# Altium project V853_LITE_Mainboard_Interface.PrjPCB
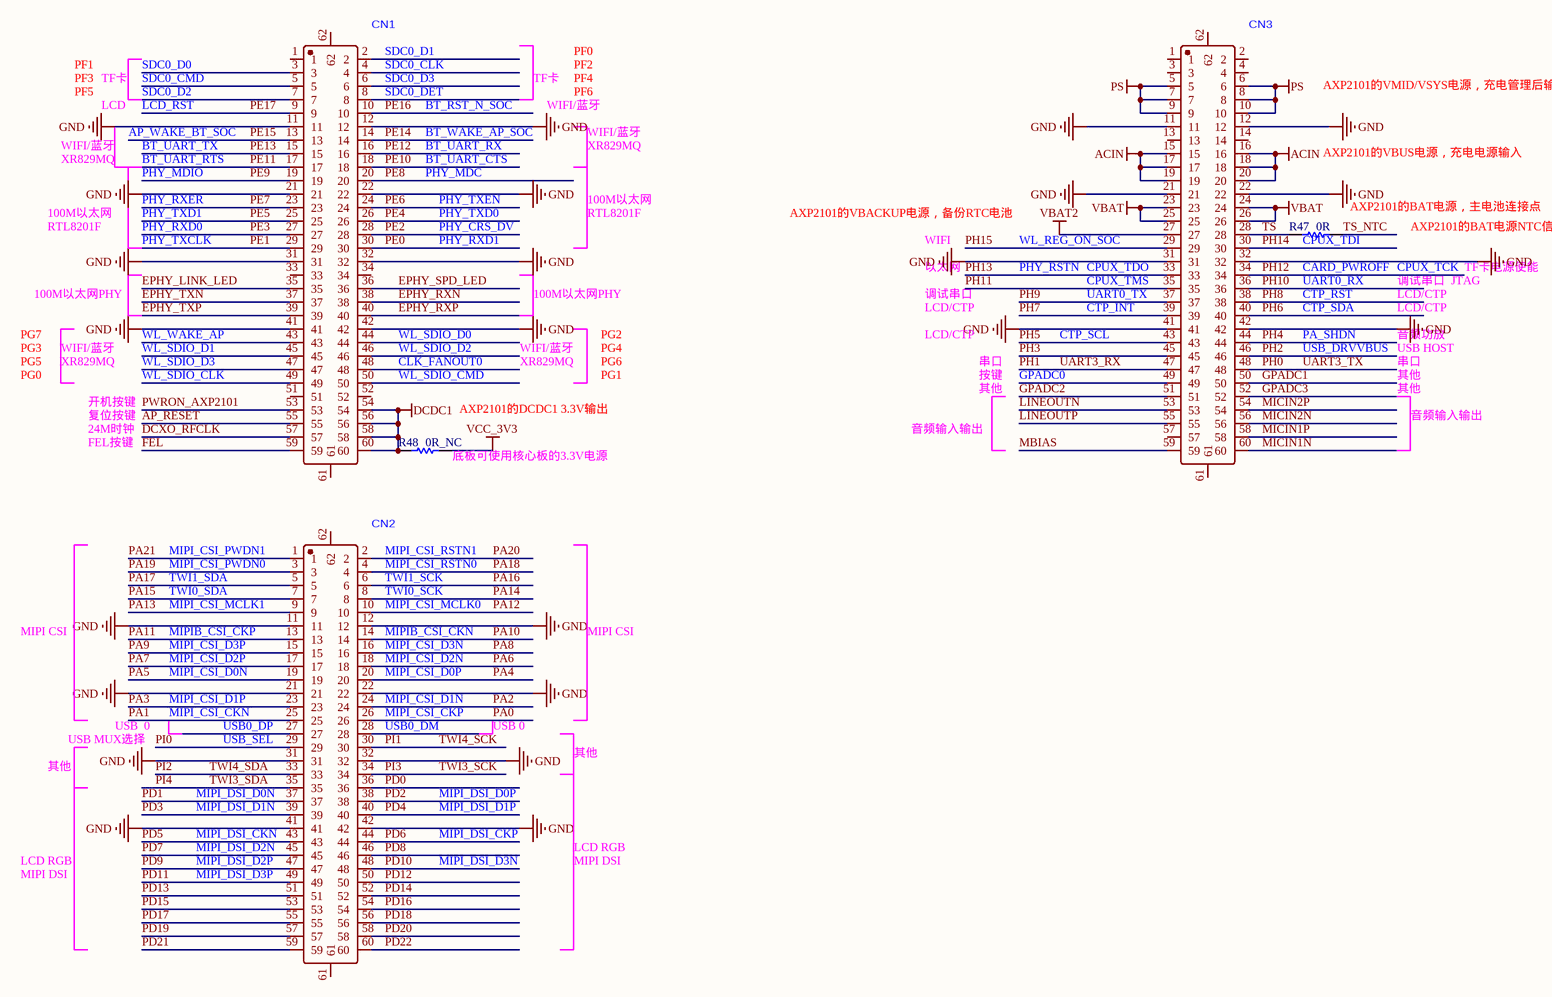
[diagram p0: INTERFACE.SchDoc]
1 sheet, 5 parts. Net scope: global (net labels, ports and power ports of the same name join across sheets).
Board file: V853_LITE_Mainboard_Interface.PcbDoc

## Sheet INTERFACE.SchDoc
size A3

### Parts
CN1  (no value)  [CONN-SMD_60P-P0.50_XKB_X0502FVS-60AS-LPSN]
CN2  (no value)  [CONN-SMD_60P-P0.50_XKB_X0502FVS-60AS-LPSN]
CN3  (no value)  [CONN-SMD_60P-P0.50_XKB_X0502FVS-60AS-LPSN]
R47  0R  [0402]
R48  0R_NC  [0805R]

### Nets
ACIN: CN3.15 CN3.16 CN3.17 CN3.18 CN3.19 CN3.20
DCDC1: CN1.54 CN1.56 CN1.58 CN1.60 R48.2
GND: CN1.11 CN1.12 CN1.21 CN1.22 CN1.31 CN1.32 CN1.41 CN1.42 CN2.11 CN2.12 CN2.21 CN2.22 CN2.31 CN2.32 CN2.41 CN2.42 CN3.11 CN3.12 CN3.21 CN3.22 CN3.31 CN3.32 CN3.41 CN3.42
PS: CN3.5 CN3.6 CN3.7 CN3.8 CN3.9 CN3.10
VBAT: CN3.23 CN3.24 CN3.25 CN3.26
VBAT2: CN3.27
VCC_3V3: R48.1
AP_RESET: CN1.55
AP_WAKE_BT_SOC: CN1.13  [also labelled PE15]
BT_RST_N_SOC: CN1.10  [also labelled PE16]
BT_UART_CTS: CN1.18  [also labelled PE10]
BT_UART_RTS: CN1.17  [also labelled PE11]
BT_UART_RX: CN1.16  [also labelled PE12]
BT_UART_TX: CN1.15  [also labelled PE13]
BT_WAKE_AP_SOC: CN1.14  [also labelled PE14]
CARD_PWROFF: CN3.34  [also labelled CPUX_TCK, PH12]
CLK_FANOUT0: CN1.48
CPUX_TDI: CN3.30  [also labelled PH14]
CPUX_TDO: CN3.33  [also labelled PH13, PHY_RSTN]
CPUX_TMS: CN3.35  [also labelled PH11]
CTP_INT: CN3.39  [also labelled PH7]
CTP_RST: CN3.38  [also labelled PH8]
CTP_SCL: CN3.43  [also labelled PH5]
CTP_SDA: CN3.40  [also labelled PH6]
DCXO_RFCLK: CN1.57
EPHY_LINK_LED: CN1.35
EPHY_RXN: CN1.38
EPHY_RXP: CN1.40
EPHY_SPD_LED: CN1.36
EPHY_TXN: CN1.37
EPHY_TXP: CN1.39
FEL: CN1.59
GPADC0: CN3.49
GPADC1: CN3.50
GPADC2: CN3.51
GPADC3: CN3.52
LCD_RST: CN1.9  [also labelled PE17]
LINEOUTN: CN3.53
LINEOUTP: CN3.55
MBIAS: CN3.59
MICIN1N: CN3.60
MICIN1P: CN3.58
MICIN2N: CN3.56
MICIN2P: CN3.54
MIPI_CSI_CKN: CN2.25  [also labelled PA1]
MIPI_CSI_CKP: CN2.26  [also labelled PA0]
MIPI_CSI_D0N: CN2.19  [also labelled PA5]
MIPI_CSI_D0P: CN2.20  [also labelled PA4]
MIPI_CSI_D1N: CN2.24  [also labelled PA2]
MIPI_CSI_D1P: CN2.23  [also labelled PA3]
MIPI_CSI_D2N: CN2.18  [also labelled PA6]
MIPI_CSI_D2P: CN2.17  [also labelled PA7]
MIPI_CSI_D3N: CN2.16  [also labelled PA8]
MIPI_CSI_D3P: CN2.15  [also labelled PA9]
MIPI_CSI_MCLK0: CN2.10  [also labelled PA12]
MIPI_CSI_MCLK1: CN2.9  [also labelled PA13]
MIPI_CSI_PWDN0: CN2.3  [also labelled PA19]
MIPI_CSI_PWDN1: CN2.1  [also labelled PA21]
MIPI_CSI_RSTN0: CN2.4  [also labelled PA18]
MIPI_CSI_RSTN1: CN2.2  [also labelled PA20]
MIPI_DSI_CKN: CN2.43  [also labelled PD5]
MIPI_DSI_CKP: CN2.44  [also labelled PD6]
MIPI_DSI_D0N: CN2.37  [also labelled PD1]
MIPI_DSI_D0P: CN2.38  [also labelled PD2]
MIPI_DSI_D1N: CN2.39  [also labelled PD3]
MIPI_DSI_D1P: CN2.40  [also labelled PD4]
MIPI_DSI_D2N: CN2.45  [also labelled PD7]
MIPI_DSI_D2P: CN2.47  [also labelled PD9]
MIPI_DSI_D3N: CN2.48  [also labelled PD10]
MIPI_DSI_D3P: CN2.49  [also labelled PD11]
MIPIB_CSI_CKN: CN2.14  [also labelled PA10]
MIPIB_CSI_CKP: CN2.13  [also labelled PA11]
PA14: CN2.8  [also labelled TWI0_SCK]
PA15: CN2.7  [also labelled TWI0_SDA]
PA16: CN2.6  [also labelled TWI1_SCK]
PA17: CN2.5  [also labelled TWI1_SDA]
PA_SHDN: CN3.44  [also labelled PH4]
PD0: CN2.36
PD8: CN2.46
PD12: CN2.50
PD13: CN2.51
PD14: CN2.52
PD15: CN2.53
PD16: CN2.54
PD17: CN2.55
PD18: CN2.56
PD19: CN2.57
PD20: CN2.58
PD21: CN2.59
PD22: CN2.60
PE0: CN1.30  [also labelled PHY_RXD1]
PE1: CN1.29  [also labelled PHY_TXCLK]
PE2: CN1.28  [also labelled PHY_CRS_DV]
PE3: CN1.27  [also labelled PHY_RXD0]
PE4: CN1.26  [also labelled PHY_TXD0]
PE5: CN1.25  [also labelled PHY_TXD1]
PE6: CN1.24  [also labelled PHY_TXEN]
PE7: CN1.23  [also labelled PHY_RXER]
PE8: CN1.20  [also labelled PHY_MDC]
PE9: CN1.19  [also labelled PHY_MDIO]
PH0: CN3.48  [also labelled UART3_TX]
PH1: CN3.47  [also labelled UART3_RX]
PH2: CN3.46  [also labelled USB_DRVVBUS]
PH3: CN3.45
PH9: CN3.37  [also labelled UART0_TX]
PH10: CN3.36  [also labelled UART0_RX]
PH15: CN3.29  [also labelled WL_REG_ON_SOC]
PI0: CN2.29  [also labelled USB_SEL]
PI1: CN2.30  [also labelled TWI4_SCK]
PI2: CN2.33  [also labelled TWI4_SDA]
PI3: CN2.34  [also labelled TWI3_SCK]
PI4: CN2.35  [also labelled TWI3_SDA]
PWRON_AXP2101: CN1.53
SDC0_CLK: CN1.4
SDC0_CMD: CN1.5
SDC0_D0: CN1.3
SDC0_D1: CN1.2
SDC0_D2: CN1.7
SDC0_D3: CN1.6
SDC0_DET: CN1.8
TS: CN3.28 R47.2
TS_NTC: R47.1
USB0_DM: CN2.28
USB0_DP: CN2.27
WL_SDIO_CLK: CN1.49
WL_SDIO_CMD: CN1.50
WL_SDIO_D0: CN1.44
WL_SDIO_D1: CN1.45
WL_SDIO_D2: CN1.46
WL_SDIO_D3: CN1.47
WL_WAKE_AP: CN1.43

Not connected (* = marked no-connect by the designer): CN1 1 33 34 51 52 61 62; CN2 61 62; CN3 1 2 3 4 13 14 57 61 62

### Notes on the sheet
- PF1
- PF0
- PF2
- PF3
- PF5
- TF卡
- LCD
- WIFI/蓝牙
- PF4
- PF6
- AXP2101的VMID/VSYS电源，充电管理后输出综合电源
- XR829MQ
- 100M以太网
- AXP2101的VBUS电源，充电电源输入
- RTL8201F
- AXP2101的VBACKUP电源，备份RTC电池
- 以太网
- WIFI
- (near R47) AXP2101的BAT电源，主电池连接点
- AXP2101的BAT电源NTC信号
- TF卡电源使能
- PG7
- 100M以太网PHY
- PG2
- 调试串口
- LCD/CTP
- 音频功放
- JTAG
- PG0
- PG3
- PG5
- 开机按键
- (near R48) AXP2101的DCDC1 3.3V输出
- PG4
- PG6
- PG1
- 串口
- 按键
- 其他
- USB HOST
- 复位按键
- 24M时钟
- FEL按键
- (near R48) 底板可使用核心板的3.3V电源
- 音频输入输出
- MIPI CSI
- USB MUX选择
- USB  0
- USB 0
- LCD RGB
- MIPI DSI

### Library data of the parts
CN1-CN3 = X0502FVS-60AS-LPSN
R47 R48 = Res1: Resistor; PartNumber: RES2.2K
